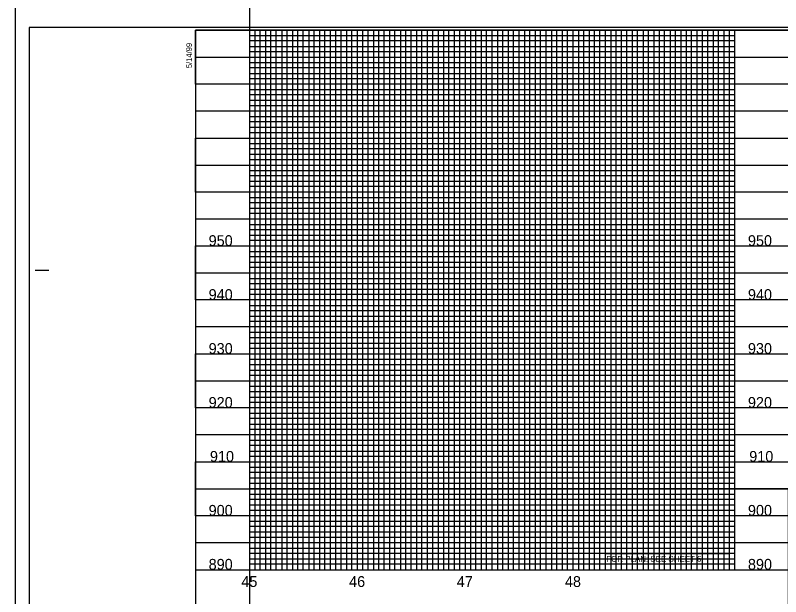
# Model space of a CAD drawing. Extents: x 1967929 to 1975641, y 546296 to 568534.
# Drawn here: x 1969864 to 1970574, y 566884 to 567423 of the extents above; entities that cross this region are included whole.
import ezdxf

# ---------------------------------------------------------------- set-up
doc = ezdxf.new("R2010")
doc.units = 0
for name, color, linetype in [('Exist Vertical Profile Horizontal Axis Label Major', 7, 'Continuous'), ('Exist Vertical Profile Vertical Axis Label', 7, 'Continuous'), ('Old_Level_41', 7, 'Continuous'), ('Old_Level_43', 7, 'Continuous'), ('Old_Level_46', 7, 'Continuous'), ('Prop Grid Mask', 7, 'Continuous'), ('Scratch_Level_3', 7, 'Continuous'), ('Sheet Cutting Line CELL', 7, 'Continuous'), ('Sheet Plot Border Inside CELL', 7, 'Continuous'), ('Sheet Plot Border Outside CELL', 7, 'Continuous'), ('Sheet Profile CELL', 7, 'Continuous'), ('Sheet Profile Grid Major CELL', 7, 'Continuous'), ('Sheet Profile Grid Middle CELL', 7, 'Continuous'), ('Sheet Profile Grid Minor CELL', 7, 'Continuous')]:
    doc.layers.add(name, color=color, linetype=linetype)

msp = doc.modelspace()

# ---------------------------------------------------------------- linework, layer by layer
at = {"layer": 'Old_Level_41'}
msp.add_line((1969882.95, 567186.36), (1969895.45, 567186.36), dxfattribs=at)
at = {"layer": 'Old_Level_43'}
msp.add_line((1970081.45, 567398.86), (1970081.45, 567398.86), dxfattribs=at)
at = {"layer": 'Old_Level_46'}
for p, q in [((1970031.45, 567408.86), (1970031.45, 567408.86)), ((1970031.45, 566883.86), (1970031.45, 566883.86))]:
    msp.add_line(p, q, dxfattribs=at)
at = {"layer": 'Prop Grid Mask'}
msp.add_lwpolyline([(1970411.53, 566923.9), (1970526.41, 566923.9), (1970526.41, 566913.87), (1970411.53, 566913.87)], close=True, dxfattribs=at)
at = {"layer": 'Scratch_Level_3'}
for points in [[(1970081.45, 567508.86), (1970081.45, 567008.86), (1971481.45, 567008.86), (1971481.5, 567312.53), (1971331.45, 567312.51), (1971331.4, 567508.86)], [(1970081.45, 567408.86), (1970081.45, 566908.86), (1971481.45, 566908.86), (1971481.5, 567212.51), (1971331.45, 567212.51), (1971331.4, 567408.86)], [(1970081.45, 567408.86), (1970081.45, 566908.86), (1971331.45, 566908.86), (1971331.45, 567177.21), (1971331.45, 567177.21), (1971331.45, 567408.86)], [(1970081.45, 566983.86), (1970081.45, 566483.86), (1970581.45, 566483.86), (1970581.45, 566683.86), (1970581.45, 566803.86), (1970581.45, 566983.86)]]:
    msp.add_lwpolyline(points, close=True, dxfattribs=at)
at = {"layer": 'Sheet Cutting Line CELL'}
msp.add_line((1969864.45, 567433.86), (1969864.45, 566333.86), dxfattribs=at)
at = {"layer": 'Sheet Plot Border Inside CELL'}
msp.add_lwpolyline([(1969877.45, 566356.31), (1971543.95, 566356.31), (1971543.95, 567411.41), (1969877.45, 567411.41)], close=True, dxfattribs=at)
at = {"layer": 'Sheet Plot Border Outside CELL'}
msp.add_lwpolyline([(1969864.45, 566333.86), (1971548.45, 566333.86), (1971548.45, 567433.86), (1969864.45, 567433.86)], close=True, dxfattribs=at)
at = {"layer": 'Sheet Profile CELL'}
msp.add_line((1970031.45, 566908.86), (1971531.45, 566908.86), dxfattribs=at)
msp.add_lwpolyline([(1971531.45, 567408.86), (1970031.45, 567408.86), (1970031.45, 566358.86), (1971531.45, 566358.86)], close=True, dxfattribs=at)
at = {"layer": 'Sheet Profile Grid Major CELL'}
for points in [[(1971331.45, 567358.86), (1970031.45, 567358.86), (1970031.45, 567408.86), (1971331.45, 567408.86)], [(1970081.45, 567408.86), (1970081.45, 566908.86), (1970131.45, 566908.86), (1970131.45, 567408.86)], [(1970181.45, 567408.86), (1970181.45, 566908.86), (1970231.45, 566908.86), (1970231.45, 567408.86)], [(1970281.45, 567408.86), (1970281.45, 566908.86), (1970331.45, 566908.86), (1970331.45, 567408.86)], [(1970381.45, 567408.86), (1970381.45, 566908.86), (1970431.45, 566908.86), (1970431.45, 567408.86)], [(1970481.45, 567408.86), (1970481.45, 566908.86), (1970531.45, 566908.86), (1970531.45, 567408.86)], [(1971331.45, 567258.86), (1970031.45, 567258.86), (1970031.45, 567308.86), (1971331.45, 567308.86)], [(1971531.45, 567158.86), (1970031.45, 567158.86), (1970031.45, 567208.86), (1971331.4, 567208.86)], [(1971531.45, 567158.86), (1970031.45, 567158.86), (1970031.45, 567208.86), (1971531.45, 567208.86)], [(1971531.45, 567058.86), (1970031.45, 567058.86), (1970031.45, 567108.86), (1971531.45, 567108.86)], [(1971531.45, 566958.86), (1970031.45, 566958.86), (1970031.45, 567008.86), (1971531.45, 567008.86)]]:
    msp.add_lwpolyline(points, dxfattribs=at)
at = {"layer": 'Sheet Profile Grid Middle CELL'}
for points in [[(1970031.45, 567408.86), (1970031.45, 567383.86), (1971331.45, 567383.86)], [(1970106.45, 566908.86), (1970106.45, 567408.86)], [(1970156.45, 567408.86), (1970156.45, 566908.86), (1970206.45, 566908.86), (1970206.45, 567408.86)], [(1970256.45, 567408.86), (1970256.45, 566908.86), (1970306.45, 566908.86), (1970306.45, 567408.86)], [(1970356.45, 567408.86), (1970356.45, 566908.86), (1970406.45, 566908.86), (1970406.45, 567408.86)], [(1970456.45, 567408.86), (1970456.45, 566908.86), (1970506.45, 566908.86), (1970506.45, 567408.86)], [(1971331.45, 567333.86), (1970031.45, 567333.86), (1970031.45, 567283.86), (1971331.45, 567283.86)], [(1971331.45, 567233.86), (1970031.45, 567233.86), (1970031.45, 567183.86), (1971331.4, 567183.86)], [(1971331.45, 567233.86), (1970031.45, 567233.86), (1970031.45, 567183.86), (1971531.45, 567183.86)], [(1971531.45, 567133.86), (1970031.45, 567133.86), (1970031.45, 567083.86), (1971531.45, 567083.86)], [(1971531.45, 567033.86), (1970031.45, 567033.86), (1970031.45, 566983.86), (1971531.45, 566983.86)], [(1971531.45, 566933.86), (1970031.45, 566933.86)]]:
    msp.add_lwpolyline(points, dxfattribs=at)
at = {"layer": 'Sheet Profile Grid Minor CELL'}
for points in [[(1970086.45, 567408.86), (1970086.45, 566908.86), (1970091.45, 566908.86), (1970091.45, 567408.86)], [(1970096.45, 567408.86), (1970096.45, 566908.86), (1970101.45, 566908.86), (1970101.45, 567408.86)], [(1970111.45, 567408.86), (1970111.45, 566908.86), (1970116.45, 566908.86), (1970116.45, 567408.86)], [(1970121.45, 567408.86), (1970121.45, 566908.86), (1970126.45, 566908.86), (1970126.45, 567408.86)], [(1970136.45, 567408.86), (1970136.45, 566908.86), (1970141.45, 566908.86), (1970141.45, 567408.86)], [(1970146.45, 567408.86), (1970146.45, 566908.86), (1970151.45, 566908.86), (1970151.45, 567408.86)], [(1970161.45, 567408.86), (1970161.45, 566908.86), (1970166.45, 566908.86), (1970166.45, 567408.86)], [(1970171.45, 567408.86), (1970171.45, 566908.86), (1970176.45, 566908.86), (1970176.45, 567408.86)], [(1970186.45, 567408.86), (1970186.45, 566908.86), (1970191.45, 566908.86), (1970191.45, 567408.86)], [(1970196.45, 567408.86), (1970196.45, 566908.86), (1970201.45, 566908.86), (1970201.45, 567408.86)], [(1970211.45, 567408.86), (1970211.45, 566908.86), (1970216.45, 566908.86), (1970216.45, 567408.86)], [(1970221.45, 567408.86), (1970221.45, 566908.86), (1970226.45, 566908.86), (1970226.45, 567408.86)], [(1970236.45, 567408.86), (1970236.45, 566908.86), (1970241.45, 566908.86), (1970241.45, 567408.86)], [(1970246.45, 566908.86), (1970251.45, 566908.86), (1970251.45, 567408.86)], [(1970246.45, 567408.86), (1970246.45, 566908.86)], [(1970261.45, 567408.86), (1970261.45, 566908.86), (1970266.45, 566908.86), (1970266.45, 567408.86)], [(1970271.45, 567408.86), (1970271.45, 566908.86), (1970276.45, 566908.86), (1970276.45, 567408.86)], [(1970286.45, 567408.86), (1970286.45, 566908.86), (1970291.45, 566908.86), (1970291.45, 567408.86)], [(1970296.45, 567408.86), (1970296.45, 566908.86), (1970301.45, 566908.86), (1970301.45, 567408.86)], [(1970311.45, 567408.86), (1970311.45, 566908.86), (1970316.45, 566908.86), (1970316.45, 567408.86)], [(1970321.45, 567408.86), (1970321.45, 566908.86), (1970326.45, 566908.86), (1970326.45, 567408.86)], [(1970336.45, 567408.86), (1970336.45, 566908.86), (1970341.45, 566908.86), (1970341.45, 567408.86)], [(1970346.45, 567408.86), (1970346.45, 566908.86), (1970351.45, 566908.86), (1970351.45, 567408.86)], [(1970361.45, 567408.86), (1970361.45, 566908.86), (1970366.45, 566908.86), (1970366.45, 567408.86)], [(1970371.45, 567408.86), (1970371.45, 566908.86), (1970376.45, 566908.86), (1970376.45, 567408.86)], [(1970386.45, 567408.86), (1970386.45, 566908.86), (1970391.45, 566908.86), (1970391.45, 567408.86)], [(1970396.45, 567408.86), (1970396.45, 566908.86), (1970401.45, 566908.86), (1970401.45, 567408.86)], [(1970411.45, 567408.86), (1970411.45, 566908.86), (1970426.45, 566908.86), (1970426.45, 567408.86)], [(1970416.45, 567408.86), (1970416.45, 566908.86), (1970421.45, 566908.86), (1970421.45, 567408.86)], [(1970436.45, 567408.86), (1970436.45, 566908.86), (1970441.45, 566908.86), (1970441.45, 567408.86)], [(1970446.45, 567408.86), (1970446.45, 566908.86), (1970451.45, 566908.86), (1970451.45, 567408.86)], [(1970461.45, 567408.86), (1970461.45, 566908.86), (1970466.45, 566908.86), (1970466.45, 567408.86)], [(1970471.45, 567408.86), (1970471.45, 566908.86), (1970476.45, 566908.86), (1970476.45, 567408.86)], [(1970486.45, 567408.86), (1970486.45, 566908.86), (1970491.45, 566908.86), (1970491.45, 567408.86)], [(1970496.45, 567408.86), (1970496.45, 566908.86), (1970501.45, 566908.86), (1970501.45, 567408.86)], [(1970511.45, 567408.86), (1970511.45, 566908.86), (1970516.45, 566908.86), (1970516.45, 567408.86)], [(1970521.45, 567408.86), (1970521.45, 566908.86), (1970526.45, 566908.86), (1970526.45, 567408.86)], [(1970081.45, 567403.86), (1970531.45, 567403.86)], [(1970531.45, 567398.86), (1970081.45, 567398.86), (1970081.45, 567393.86), (1970531.45, 567393.86)], [(1970531.45, 567388.86), (1970081.45, 567388.86), (1970081.45, 567378.86), (1970531.45, 567378.86)], [(1970531.45, 567373.86), (1970081.45, 567373.86), (1970081.45, 567368.86), (1970531.45, 567368.86)], [(1970531.45, 567363.86), (1970081.45, 567363.86), (1970081.45, 567353.86), (1970531.45, 567353.86)], [(1970531.45, 567348.86), (1970081.45, 567348.86), (1970081.45, 567343.86), (1970531.45, 567343.86)], [(1970531.45, 567338.86), (1970081.45, 567338.86), (1970081.45, 567328.86), (1970531.45, 567328.86)], [(1970531.45, 567323.86), (1970081.45, 567323.86), (1970081.45, 567318.86), (1970531.45, 567318.86)], [(1970531.45, 567313.86), (1970081.45, 567313.86), (1970081.45, 567303.86), (1970531.45, 567303.86)], [(1970531.45, 567298.86), (1970081.45, 567298.86), (1970081.45, 567293.86), (1970531.45, 567293.86)], [(1970531.45, 567288.86), (1970081.45, 567288.86), (1970081.45, 567278.86), (1970531.45, 567278.86)], [(1970531.45, 567273.86), (1970081.45, 567273.86), (1970081.45, 567268.86), (1970531.45, 567268.86)], [(1970531.45, 567263.86), (1970081.45, 567263.86), (1970081.45, 567253.86), (1970531.45, 567253.86)], [(1970531.45, 567248.86), (1970081.45, 567248.86), (1970081.45, 567243.86), (1970531.45, 567243.86)], [(1970531.45, 567238.86), (1970081.45, 567238.86), (1970081.45, 567228.86), (1970531.45, 567228.86)], [(1970531.45, 567223.86), (1970081.45, 567223.86), (1970081.45, 567218.86), (1970531.45, 567218.86)], [(1970531.45, 567213.86), (1970081.45, 567213.86), (1970081.45, 567203.86), (1970531.45, 567203.86)], [(1970531.45, 567198.86), (1970081.45, 567198.86), (1970081.45, 567193.86), (1970531.45, 567193.86)], [(1970531.45, 567188.86), (1970081.45, 567188.86), (1970081.45, 567178.86), (1970531.45, 567178.86)], [(1970531.45, 567173.86), (1970081.45, 567173.86), (1970081.45, 567168.86), (1970531.45, 567168.86)], [(1970531.45, 567163.86), (1970081.45, 567163.86), (1970081.45, 567153.86), (1970531.45, 567153.86)], [(1970531.45, 567148.86), (1970081.45, 567148.86), (1970081.45, 567143.86), (1970531.45, 567143.86)], [(1970531.45, 567138.86), (1970081.45, 567138.86), (1970081.45, 567128.86), (1970531.45, 567128.86)], [(1970531.45, 567123.86), (1970081.45, 567123.86), (1970081.45, 567118.86), (1970531.45, 567118.86)], [(1970531.45, 567113.86), (1970081.45, 567113.86)], [(1970081.45, 567103.86), (1970531.45, 567103.86)], [(1970531.45, 567098.86), (1970081.45, 567098.86), (1970081.45, 567093.86), (1970531.45, 567093.86)], [(1970531.45, 567088.86), (1970081.45, 567088.86)], [(1970081.45, 567078.86), (1970531.45, 567078.86)], [(1970531.45, 567073.86), (1970081.45, 567073.86), (1970081.45, 567068.86), (1970531.45, 567068.86)], [(1970531.45, 567063.86), (1970081.45, 567063.86), (1970081.45, 567053.86), (1970531.45, 567053.86)], [(1970531.45, 567048.86), (1970081.45, 567048.86), (1970081.45, 567043.86), (1970531.45, 567043.86)], [(1970531.45, 567038.86), (1970081.45, 567038.86), (1970081.45, 567028.86), (1970531.45, 567028.86)], [(1970531.45, 567023.86), (1970081.45, 567023.86), (1970081.45, 567018.86), (1970531.45, 567018.86)], [(1970531.45, 567013.86), (1970081.45, 567013.86), (1970081.45, 567003.86), (1970531.45, 567003.86)], [(1970531.45, 566998.86), (1970081.45, 566998.86), (1970081.45, 566993.86), (1970531.45, 566993.86)], [(1970531.45, 566988.86), (1970081.45, 566988.86), (1970081.45, 566978.86), (1970531.45, 566978.86)], [(1970531.45, 566973.86), (1970081.45, 566973.86), (1970081.45, 566968.86), (1970531.45, 566968.86)], [(1970531.45, 566963.86), (1970081.45, 566963.86), (1970081.45, 566953.86), (1970531.45, 566953.86)], [(1970531.45, 566948.86), (1970081.45, 566948.86), (1970081.45, 566943.86), (1970531.45, 566943.86)], [(1970531.45, 566938.86), (1970081.45, 566938.86), (1970081.45, 566928.86), (1970531.45, 566928.86)], [(1970531.45, 566923.86), (1970081.45, 566923.86), (1970081.45, 566918.86), (1970531.45, 566918.86)], [(1970531.45, 566913.86), (1970081.45, 566913.86), (1970081.45, 566908.86), (1971481.45, 566908.86)]]:
    msp.add_lwpolyline(points, dxfattribs=at)

# ---------------------------------------------------------------- texts
at = {"layer": 'Exist Vertical Profile Horizontal Axis Label Major'}
for s, p in [('46', (1970173.93, 566892.89)), ('48', (1970374.03, 566892.89)), ('45', (1970073.99, 566892.89)), ('47', (1970273.79, 566892.89))]:
    msp.add_text(s, height=10, dxfattribs=at).set_placement(p)
at = {"layer": 'Exist Vertical Profile Vertical Axis Label'}
for s, p in [('950', (1970043.69, 567208.86)), ('950', (1970543.69, 567208.86)), ('940', (1970043.69, 567158.86)), ('940', (1970543.69, 567158.86)), ('930', (1970043.69, 567108.86)), ('930', (1970543.69, 567108.86)), ('920', (1970043.69, 567058.86)), ('920', (1970543.69, 567058.86)), ('910', (1970044.89, 567008.86)), ('910', (1970544.89, 567008.86)), ('900', (1970043.69, 566958.86)), ('900', (1970543.69, 566958.86)), ('890', (1970043.69, 566908.86)), ('890', (1970543.69, 566908.86))]:
    msp.add_text(s, height=10, dxfattribs=at).set_placement(p)
at = {"layer": 'Prop Grid Mask'}
msp.add_text('FOR PLAN: SEE SHEET 6', height=5.4932, dxfattribs=at).set_placement((1970412.42, 566916.16))
at = {"layer": 'Sheet Profile CELL'}
msp.add_text('5/14/99', height=5.25, rotation=90, dxfattribs=at).set_placement((1970028.2, 567373.66))

doc.saveas('drawing.dxf')
